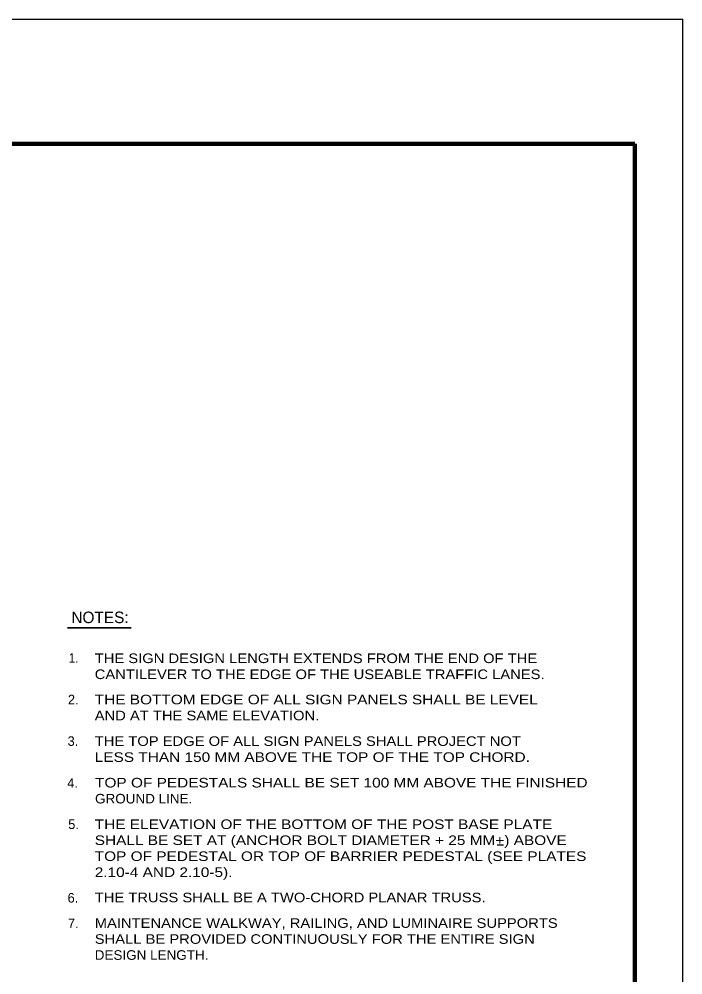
# Model space of a CAD drawing. Extents: x 312601.858 to 312602.699, y 144420.109 to 144420.704.
# Drawn here: x 312602.4911 to 312602.6988, y 144420.4046 to 144420.7035 of the extents above; entities that cross this region are included whole.
import ezdxf
from ezdxf.enums import TextEntityAlignment as Align

# ---------------------------------------------------------------- set-up
doc = ezdxf.new("R2010")
doc.units = 0
doc.header["$LTSCALE"] = 0.0012
doc.layers.add('1', color=7, linetype='Continuous', lineweight=13)
doc.layers.add('39', color=7, linetype='Continuous', lineweight=13)

msp = doc.modelspace()

# ---------------------------------------------------------------- linework, layer by layer
at = {"layer": '1', "lineweight": 25}
msp.add_line((312601.8578, 144420.7035), (312602.6988, 144420.7035), dxfattribs=at)
msp.add_lwpolyline([(312601.8578, 144420.1095), (312602.6988, 144420.1095), (312602.6988, 144420.7035)], dxfattribs=at)
at = {"layer": '39', "lineweight": 25}
for p, q in [((312602.6988, 144420.1095), (312602.6988, 144420.7035)), ((312602.5735, 144420.6645), (312602.6838, 144420.6645)), ((312602.6838, 144420.6514), (312602.6838, 144420.6645)), ((312602.6407, 144420.4453), (312602.6427, 144420.4453))]:
    msp.add_line(p, q, dxfattribs=at)
at = {"layer": '39', "lineweight": 158}
for p in [(312601.9088, 144420.6645), (312602.6838, 144420.1247)]:
    msp.add_line(p, (312602.6838, 144420.6645), dxfattribs=at)
at = {"layer": '39', "lineweight": 35}
msp.add_line((312602.5063, 144420.5131), (312602.5262, 144420.5131), dxfattribs=at)

# ---------------------------------------------------------------- texts
at = {"layer": '1'}
for s, width, p in [('1.', 0.9, (312602.5067, 144420.5022)), ('THE SIGN DESIGN LENGTH EXTENDS FROM THE END OF THE', 1.15, (312602.5148, 144420.5021)), ('CANTILEVER TO THE EDGE OF THE USEABLE TRAFFIC LANES.', 1.15, (312602.5148, 144420.4971))]:
    msp.add_text(s, height=0.003, dxfattribs=dict(at, width=width)).set_placement(p)
for s, p in [('2.', (312602.5064, 144420.4892)), ('3.', (312602.5063, 144420.4762)), ('4.', (312602.5062, 144420.4631)), ('5.', (312602.5065, 144420.4502)), ('6.', (312602.5063, 144420.4272)), ('7.', (312602.5064, 144420.4192))]:
    msp.add_text(s, height=0.003, dxfattribs=at).set_placement(p)
at = {"layer": '39'}
msp.add_text('NOTES:', height=0.0036, dxfattribs=at).set_placement((312602.51645, 144420.5146), align=Align.CENTER)
for s, width, p in [('THE BOTTOM EDGE OF ALL SIGN PANELS SHALL BE LEVEL', 1.2, (312602.5148, 144420.4892)), ('AND AT THE SAME ELEVATION.', 1.15, (312602.5148, 144420.4842)), ('THE TOP EDGE OF ALL SIGN PANELS SHALL PROJECT NOT', 1.15, (312602.5148, 144420.4762)), ('LESS THAN 150 MM ABOVE THE TOP OF THE TOP CHORD.', 1.2, (312602.5148, 144420.4712)), ('TOP OF PEDESTALS SHALL BE SET 100 MM ABOVE THE FINISHED', 1.2, (312602.5149, 144420.4632)), ('GROUND LINE.', 1.05, (312602.5149, 144420.4582)), ('THE ELEVATION OF THE BOTTOM OF THE POST BASE PLATE ', 1.2, (312602.5148, 144420.4502)), ('SHALL BE SET AT (ANCHOR BOLT DIAMETER + 25 MM+) ABOVE ', 1.2, (312602.5148, 144420.4452)), ('TOP OF PEDESTAL OR TOP OF BARRIER PEDESTAL (SEE PLATES ', 1.2, (312602.5148, 144420.4402)), ('2.10-4 AND 2.10-5).', 1.2, (312602.5148, 144420.4352)), ('THE TRUSS SHALL BE A TWO-CHORD PLANAR TRUSS.', 1.15, (312602.5148, 144420.4273)), ('MAINTENANCE WALKWAY, RAILING, AND LUMINAIRE SUPPORTS', 1.15, (312602.5148, 144420.4193)), ('SHALL BE PROVIDED CONTINUOUSLY FOR THE ENTIRE SIGN', 1.15, (312602.5148, 144420.4143)), ('DESIGN LENGTH.', 1.05, (312602.5148, 144420.4093))]:
    msp.add_text(s, height=0.003, dxfattribs=dict(at, width=width)).set_placement(p)

doc.saveas('drawing.dxf')
